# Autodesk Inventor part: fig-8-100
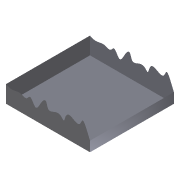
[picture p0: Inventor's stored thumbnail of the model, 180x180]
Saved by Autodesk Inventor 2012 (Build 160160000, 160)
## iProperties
Shininess: 64.0
Length Units: 11269
Angle Units: 11279
Time Units: 11290
Mass Units: 11283
Length Display Precision: 3
Angle Display Precision: 2
Compacted: True
Part Number: fig-8-100
Document SubType Name: Modeling
Created: 2002-12
Designer: deepak
Density: 1 g/cm^3
Material: Default
Surface Area: 62.5725 cm^2
Density: 0.0
Volumn: 0.0
Area: 0.0
PropertySet Name: Model Information
Control State: 0
Master: False
Checked Out: False
Author: deepak
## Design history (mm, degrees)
sketch "Sketch1"
  geometry: L1 (-32.188, 30.089)-(27.812, 30.089); L2 (27.812, 30.089)-(27.812, -29.911); L3 (27.812, -29.911)-(-32.188, -29.911); L4 (-32.188, -29.911)-(-32.188, 30.089)
  constraints: 8 end point, 2 parallel, 1 horizontal, 1 perpendicular
  dimensions: "d0" = 60 distance of L1.start L1.end; "d1" = 60 distance of L3.end L1.start
extrude "Extrusion1" new body sketch "Sketch1" stored distance "d2" = 20; taper "d3" = 0 deg
sketch "Sketch2"
  geometry: 17 further points
  constraints: 17 other
extrude_surface "ExtrusionSrf1" sketch "Sketch2" dims "d4" = 70, "d5" = 0
split "Split1"
delete_face "Delete Face2"
body "Solid1"
body "Srf1"
